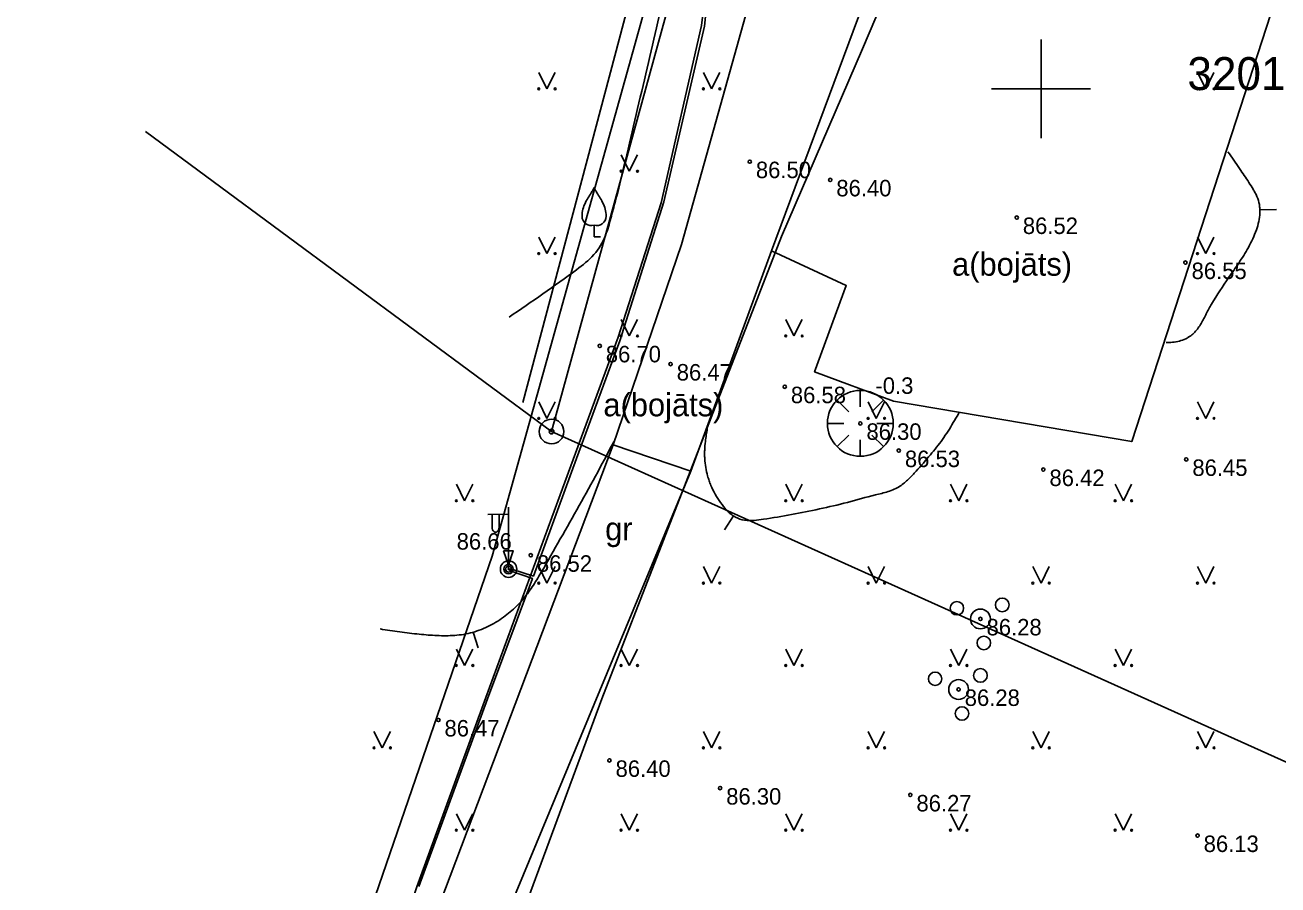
# Model space of a CAD drawing. Extents: x 576692 to 577659, y 273254 to 273799.
# Drawn here: x 576719.16 to 576757.19, y 273675.84 to 273701.94 of the extents above; entities that cross this region are included whole.
import ezdxf

# ---------------------------------------------------------------- set-up
doc = ezdxf.new("R2010")
doc.units = 0
for name, color, linetype in [('APGS_ELEM_####_####_#', 7, 'Continuous'), ('BUVE_EKAS_BPAL_####_#', 7, 'Continuous'), ('BUVE_EKAS_RAKS_TKST_#', 7, 'Continuous'), ('CELI_CAPM_####_####_#', 7, 'Continuous'), ('CELI_CMAL_####_####_#', 7, 'Continuous'), ('CELI_TAKA_####_####_#', 7, 'Continuous'), ('CKOM_ELEM_####_####_#', 7, 'Continuous'), ('GEOD_SITP_####_TKST_#', 7, 'Continuous'), ('HIDT_REZV_####_TKST_#', 7, 'Continuous'), ('LKAN_ELEM_PAST_TKST_#', 7, 'Continuous'), ('LKAN_VADP_PAST_####_#', 7, 'Continuous'), ('RELJ_ELEM_####_####_#', 7, 'Continuous'), ('ROBZ_PROJ_####_TKST_#', 7, 'Continuous'), ('SILT_VADP_UDEN_####_#', 7, 'Continuous'), ('TERT_DIAM_####_TKST_#', 7, 'Continuous'), ('TERT_KONT_####_####_#', 7, 'Continuous'), ('TERT_KRND_####_####_#', 7, 'Continuous'), ('UDTK_VADP_UDEN_TKST_#', 7, 'Continuous')]:
    doc.layers.add(name, color=color, linetype=linetype)

msp = doc.modelspace()

# ---------------------------------------------------------------- linework, layer by layer
at = {"layer": 'APGS_ELEM_####_####_#'}
msp.add_lwpolyline([(576737.011, 273689.199), (576739.373, 273688.394)], dxfattribs=at)
at = {"layer": 'BUVE_EKAS_RAKS_TKST_#'}
for radius in [0.375, 0.0702]:
    msp.add_circle((576735.14, 273689.6), radius, dxfattribs=at)
at = {"layer": 'CELI_CAPM_####_####_#'}
for points in [[(576748.236, 273714.891), (576752.784, 273713.881), (576754.719, 273717.805), (576756.542, 273719.356), (576769.187, 273719.688), (576767.146, 273715.06), (576764.561, 273707.822), (576760.708, 273708.626), (576758.033, 273705.522), (576752.756, 273689.295), (576745.525, 273690.518), (576743.128, 273691.407), (576744.089, 273694.027), (576741.816, 273695.089)], [(576747.985, 273714.221), (576746.348, 273707.285), (576741.816, 273695.089), (576739.373, 273688.394), (576733.496, 273674.256)], [(576731.578, 273674.82), (576737.011, 273689.199), (576739.086, 273695.273), (576742.568, 273707.72)]]:
    msp.add_lwpolyline(points, dxfattribs=at)
at = {"layer": 'CELI_TAKA_####_####_#'}
msp.add_lwpolyline([(576848.447, 273595.284), (576850.413, 273611.975), (576839.74, 273611.3), (576799.298, 273680.086), (576786.491, 273690.257), (576780.2, 273683.233), (576786.155, 273661.79), (576765.1, 273656.565), (576764.662, 273653.384), (576732.149, 273649.138), (576726.076, 273650.997), (576719.157, 273649.712), (576724.595, 273660.398), (576733.342, 273685.822), (576746.079, 273731.492)], dxfattribs=at)
at = {"layer": 'CKOM_ELEM_####_####_#'}
for p, q in [((576750, 273701.5), (576750, 273700)), ((576748.5, 273700), (576750, 273700)), ((576750, 273700), (576750, 273698.5)), ((576750, 273700), (576751.5, 273700))]:
    msp.add_line(p, q, dxfattribs=at)
at = {"layer": 'GEOD_SITP_####_TKST_#'}
for p, q in [((576757.144, 273696.337), (576756.644, 273696.324)), ((576740.392, 273686.617), (576740.661, 273687.038)), ((576732.909, 273683.033), (576732.763, 273683.511))]:
    msp.add_line(p, q, dxfattribs=at)
for points in [[(576743.18, 273721.579), (576742.673, 273719.416), (576742.4, 273718.16), (576742.151, 273716.898), (576741.901, 273715.637), (576741.627, 273714.381), (576741.252, 273712.992), (576740.821, 273711.619), (576740.384, 273710.247), (576739.993, 273708.863), (576739.309, 273706.065), (576738.651, 273703.26), (576738, 273700.452), (576737.339, 273697.647), (576737.081, 273696.597), (576736.938, 273696.074), (576736.779, 273695.554), (576736.425, 273694.968), (576735.899, 273694.512), (576733.849, 273693.07)], [(576755.676, 273698.093), (576756.029, 273697.579), (576756.31, 273697.162), (576756.44, 273696.955), (576756.498, 273696.848), (576756.553, 273696.738), (576756.628, 273696.486), (576756.642, 273696.358), (576756.644, 273696.232), (576756.612, 273695.974), (576756.537, 273695.718), (576756.295, 273695.19), (576756.001, 273694.709), (576755.696, 273694.272), (576755.179, 273693.469), (576755.096, 273693.325), (576755.018, 273693.177), (576754.941, 273693.029), (576754.86, 273692.883), (576754.666, 273692.617), (576754.543, 273692.507), (576754.472, 273692.46), (576754.394, 273692.418), (576753.994, 273692.308), (576753.795, 273692.3)], [(576747.518, 273690.181), (576747.491, 273690.135), (576747.335, 273689.871), (576747.009, 273689.36), (576746.641, 273688.895), (576746.209, 273688.397), (576745.978, 273688.157), (576745.853, 273688.046), (576745.718, 273687.943), (576745.356, 273687.778), (576744.97, 273687.677), (576744.121, 273687.449), (576743.271, 273687.25), (576742.421, 273687.08), (576741.571, 273686.936), (576741.288, 273686.902), (576741.003, 273686.911), (576740.725, 273687.001), (576740.59, 273687.089), (576740.524, 273687.145), (576740.46, 273687.211), (576740.11, 273687.698), (576739.978, 273687.966), (576739.924, 273688.107), (576739.879, 273688.252), (576739.791, 273688.775), (576739.787, 273688.906), (576739.789, 273689.037), (576739.811, 273689.298), (576739.868, 273689.693)], [(576737.032, 273689.301), (576737.016, 273689.27), (576736.472, 273688.243), (576735.91, 273687.226), (576735.335, 273686.216), (576734.755, 273685.208), (576734.481, 273684.781), (576734.164, 273684.39), (576733.787, 273684.043), (576733.57, 273683.887), (576733.332, 273683.745), (576732.811, 273683.526), (576732.541, 273683.457), (576732.266, 273683.419), (576731.731, 273683.406), (576731.197, 273683.442), (576730.606, 273683.511), (576730.013, 273683.596), (576729.942, 273683.608)]]:
    msp.add_spline(points, degree=3, dxfattribs=at)
at = {"layer": 'LKAN_ELEM_PAST_TKST_#'}
for p, q in [((576734.75, 273700.5), (576735, 273700)), ((576735, 273700), (576735.25, 273700.5)), ((576739.75, 273700.5), (576740, 273700)), ((576740, 273700), (576740.25, 273700.5)), ((576754.75, 273700.5), (576755, 273700)), ((576755, 273700), (576755.25, 273700.5)), ((576737.25, 273698), (576737.5, 273697.5)), ((576737.5, 273697.5), (576737.75, 273698)), ((576734.75, 273695.5), (576735, 273695)), ((576735, 273695), (576735.25, 273695.5)), ((576736.431, 273695.86), (576736.431, 273695.508)), ((576736.431, 273695.508), (576736.631, 273695.508)), ((576754.75, 273695.5), (576755, 273695)), ((576755, 273695), (576755.25, 273695.5)), ((576737.25, 273693), (576737.5, 273692.5)), ((576737.5, 273692.5), (576737.75, 273693)), ((576742.25, 273693), (576742.5, 273692.5)), ((576742.5, 273692.5), (576742.75, 273693)), ((576734.75, 273690.5), (576735, 273690)), ((576735, 273690), (576735.25, 273690.5)), ((576744.75, 273690.5), (576745, 273690)), ((576745, 273690), (576745.25, 273690.5)), ((576754.75, 273690.5), (576755, 273690)), ((576755, 273690), (576755.25, 273690.5)), ((576732.25, 273688), (576732.5, 273687.5)), ((576732.5, 273687.5), (576732.75, 273688)), ((576742.25, 273688), (576742.5, 273687.5)), ((576742.5, 273687.5), (576742.75, 273688)), ((576747.25, 273688), (576747.5, 273687.5)), ((576747.5, 273687.5), (576747.75, 273688)), ((576752.25, 273688), (576752.5, 273687.5)), ((576752.5, 273687.5), (576752.75, 273688)), ((576734.75, 273685.5), (576735, 273685)), ((576735, 273685), (576735.25, 273685.5)), ((576739.75, 273685.5), (576740, 273685)), ((576740, 273685), (576740.25, 273685.5)), ((576744.75, 273685.5), (576745, 273685)), ((576745, 273685), (576745.25, 273685.5)), ((576749.75, 273685.5), (576750, 273685)), ((576750, 273685), (576750.25, 273685.5)), ((576754.75, 273685.5), (576755, 273685)), ((576755, 273685), (576755.25, 273685.5)), ((576732.25, 273683), (576732.5, 273682.5)), ((576732.5, 273682.5), (576732.75, 273683)), ((576737.25, 273683), (576737.5, 273682.5)), ((576737.5, 273682.5), (576737.75, 273683)), ((576742.25, 273683), (576742.5, 273682.5)), ((576742.5, 273682.5), (576742.75, 273683)), ((576747.25, 273683), (576747.5, 273682.5)), ((576747.5, 273682.5), (576747.75, 273683)), ((576752.25, 273683), (576752.5, 273682.5)), ((576752.5, 273682.5), (576752.75, 273683)), ((576729.75, 273680.5), (576730, 273680)), ((576730, 273680), (576730.25, 273680.5)), ((576739.75, 273680.5), (576740, 273680)), ((576740, 273680), (576740.25, 273680.5)), ((576744.75, 273680.5), (576745, 273680)), ((576745, 273680), (576745.25, 273680.5)), ((576749.75, 273680.5), (576750, 273680)), ((576750, 273680), (576750.25, 273680.5)), ((576754.75, 273680.5), (576755, 273680)), ((576755, 273680), (576755.25, 273680.5)), ((576732.25, 273678), (576732.5, 273677.5)), ((576732.5, 273677.5), (576732.75, 273678)), ((576737.25, 273678), (576737.5, 273677.5)), ((576737.5, 273677.5), (576737.75, 273678)), ((576742.25, 273678), (576742.5, 273677.5)), ((576742.5, 273677.5), (576742.75, 273678)), ((576747.25, 273678), (576747.5, 273677.5)), ((576747.5, 273677.5), (576747.75, 273678)), ((576752.25, 273678), (576752.5, 273677.5)), ((576752.5, 273677.5), (576752.75, 273678))]:
    msp.add_line(p, q, dxfattribs=at)
for centre, radius in [((576734.75, 273700), 0.028), ((576735.25, 273700), 0.0263), ((576739.75, 273700), 0.028), ((576740.25, 273700), 0.0263), ((576754.75, 273700), 0.028), ((576755.25, 273700), 0.0263), ((576737.25, 273697.5), 0.028), ((576737.75, 273697.5), 0.0263), ((576734.75, 273695), 0.028), ((576735.25, 273695), 0.0263), ((576754.75, 273695), 0.028), ((576755.25, 273695), 0.0263), ((576737.25, 273692.5), 0.028), ((576737.75, 273692.5), 0.0263), ((576742.25, 273692.5), 0.028), ((576742.75, 273692.5), 0.0263), ((576734.75, 273690), 0.028), ((576735.25, 273690), 0.0263), ((576744.75, 273690), 0.028), ((576745.25, 273690), 0.0263), ((576754.75, 273690), 0.028), ((576755.25, 273690), 0.0263), ((576732.25, 273687.5), 0.028), ((576732.75, 273687.5), 0.0263), ((576742.25, 273687.5), 0.028), ((576742.75, 273687.5), 0.0263), ((576747.25, 273687.5), 0.028), ((576747.75, 273687.5), 0.0263), ((576752.25, 273687.5), 0.028), ((576752.75, 273687.5), 0.0263), ((576734.75, 273685), 0.028), ((576735.25, 273685), 0.0263), ((576739.75, 273685), 0.028), ((576740.25, 273685), 0.0263), ((576744.75, 273685), 0.028), ((576745.25, 273685), 0.0263), ((576749.75, 273685), 0.028), ((576750.25, 273685), 0.0263), ((576754.75, 273685), 0.028), ((576755.25, 273685), 0.0263), ((576748.822, 273684.338), 0.207), ((576747.447, 273684.237), 0.204), ((576748.161, 273683.913), 0.301), ((576748.264, 273683.185), 0.205), ((576732.25, 273682.5), 0.028), ((576732.75, 273682.5), 0.0263), ((576737.25, 273682.5), 0.028), ((576737.75, 273682.5), 0.0263), ((576742.25, 273682.5), 0.028), ((576742.75, 273682.5), 0.0263), ((576746.784, 273682.096), 0.204), ((576747.25, 273682.5), 0.028), ((576747.75, 273682.5), 0.0263), ((576748.159, 273682.197), 0.207), ((576752.25, 273682.5), 0.028), ((576752.75, 273682.5), 0.0263), ((576747.498, 273681.772), 0.301), ((576747.601, 273681.044), 0.205), ((576729.75, 273680), 0.028), ((576730.25, 273680), 0.0263), ((576739.75, 273680), 0.028), ((576740.25, 273680), 0.0263), ((576744.75, 273680), 0.028), ((576745.25, 273680), 0.0263), ((576749.75, 273680), 0.028), ((576750.25, 273680), 0.0263), ((576754.75, 273680), 0.028), ((576755.25, 273680), 0.0263), ((576732.25, 273677.5), 0.028), ((576732.75, 273677.5), 0.0263), ((576737.25, 273677.5), 0.028), ((576737.75, 273677.5), 0.0263), ((576742.25, 273677.5), 0.028), ((576742.75, 273677.5), 0.0263), ((576747.25, 273677.5), 0.028), ((576747.75, 273677.5), 0.0263), ((576752.25, 273677.5), 0.028), ((576752.75, 273677.5), 0.0263)]:
    msp.add_circle(centre, radius, dxfattribs=at)
for centre, radius, start, end in [((576749.056, 273689.112), 14.88, 148.4844, 149.9901), ((576736.014, 273697.146), 0.439, 324.3837, 341.712), ((576736.848, 273697.146), 0.439, 198.288, 215.6163), ((576723.806, 273689.112), 14.88, 30.0099, 31.5156), ((576736.955, 273696.133), 0.89, 151.757, 179.9138), ((576735.907, 273696.133), 0.89, 0.0862, 28.243), ((576736.355, 273696.139), 0.29, 181.0782, 285.2823), ((576736.507, 273696.139), 0.29, 254.7177, 358.9218)]:
    msp.add_arc(centre, radius, start, end, dxfattribs=at)
at = {"layer": 'RELJ_ELEM_####_####_#'}
for p, q in [((576743.807, 273690.555), (576744.161, 273690.201)), ((576744.514, 273690.848), (576744.514, 273690.348)), ((576744.868, 273690.201), (576745.221, 273690.555)), ((576743.514, 273689.848), (576744.014, 273689.848)), ((576745.014, 273689.848), (576745.514, 273689.848)), ((576743.807, 273689.141), (576744.161, 273689.494)), ((576744.868, 273689.494), (576745.221, 273689.141)), ((576744.514, 273689.348), (576744.514, 273688.848))]:
    msp.add_line(p, q, dxfattribs=at)
msp.add_lwpolyline([(576733.68, 273685.975), (576733.98, 273685.975), (576733.83, 273685.542)], close=True, dxfattribs=at)
for centre, radius in [((576741.158, 273697.79), 0.05), ((576743.6, 273697.237), 0.05), ((576749.262, 273696.095), 0.05), ((576754.385, 273694.727), 0.05), ((576736.602, 273692.2), 0.05), ((576738.755, 273691.648), 0.05), ((576742.219, 273690.96), 0.05), ((576744.514, 273689.848), 1), ((576744.514, 273689.848), 0.05), ((576745.682, 273689.021), 0.05), ((576754.409, 273688.753), 0.05), ((576750.07, 273688.445), 0.05), ((576734.511, 273685.845), 0.05), ((576748.161, 273683.913), 0.05), ((576747.498, 273681.772), 0.05), ((576731.704, 273680.845), 0.05), ((576736.898, 273679.62), 0.05), ((576740.257, 273678.778), 0.05), ((576746.032, 273678.571), 0.05), ((576754.752, 273677.339), 0.05)]:
    msp.add_circle(centre, radius, dxfattribs=at)
at = {"layer": 'ROBZ_PROJ_####_TKST_#'}
msp.add_lwpolyline([(576726.076, 273650.997), (576727.932, 273656.567), (576729.5, 273661.655), (576730.682, 273665.084), (576731.865, 273668.514), (576734.264, 273674.998), (576736.663, 273681.483), (576738.539, 273686.307), (576742.122, 273695.516), (576744.578, 273701.213), (576746.572, 273705.904), (576748.565, 273710.596)], dxfattribs=at)
at = {"layer": 'SILT_VADP_UDEN_####_#'}
for points in [[(576829.949, 273731.794), (576819.3, 273727.418), (576775.79, 273724.09), (576773.75, 273720.17), (576743.03, 273718.32), (576735.14, 273689.6), (576722.81, 273698.708)], [(576722.81, 273698.708), (576735.14, 273689.6), (576764.98, 273676.18), (576776.102, 273646.342)]]:
    msp.add_lwpolyline(points, dxfattribs=at)
msp.add_lwpolyline([(576735.14, 273689.6), (576743.03, 273718.32), (576773.75, 273720.17), (576765.79, 273703), (576762.48, 273692.95), (576762.24, 273683.67), (576764.98, 273676.18)], close=True, dxfattribs=at)
at = {"layer": 'TERT_DIAM_####_TKST_#'}
for p, q in [((576733.836, 273685.424), (576733.836, 273687.307)), ((576733.836, 273687.091), (576733.201, 273687.086)), ((576733.336, 273687.087), (576733.336, 273686.695)), ((576733.546, 273687.089), (576733.546, 273686.695))]:
    msp.add_line(p, q, dxfattribs=at)
for radius in [0.25, 0.09]:
    msp.add_circle((576733.836, 273685.424), radius, dxfattribs=at)
msp.add_ellipse((576733.441, 273686.695), major_axis=(0, 0.151), ratio=0.695971, start_param=1.570796, end_param=4.712389, dxfattribs=at)
at = {"layer": 'TERT_KONT_####_####_#'}
for radius in [0.141, 0.0126]:
    msp.add_circle((576733.836, 273685.424), radius, dxfattribs=at)
at = {"layer": 'TERT_KRND_####_####_#'}
for points in [[(576721.135, 273650.079), (576722.114, 273651.858), (576722.686, 273652.958), (576723.259, 273654.059), (576724.172, 273656.131), (576725.085, 273658.204), (576725.929, 273659.674), (576727.286, 273664.024), (576728.643, 273668.374), (576729.188, 273670.049), (576731.053, 273675.786), (576733.142, 273681.529), (576735.152, 273686.994), (576737.161, 273692.459), (576738.469, 273696.545), (576739.694, 273701.926), (576740.457, 273708.29), (576741.181, 273711.29), (576742.084, 273714.417), (576742.987, 273717.544), (576742.985, 273717.979), (576742.779, 273718.232), (576742.37, 273718.284)], [(576743.072, 273718.011), (576743.069, 273717.562), (576742.171, 273714.428), (576741.272, 273711.293), (576740.524, 273708.289), (576740.284, 273706.674), (576739.78, 273701.905), (576738.545, 273696.569), (576737.21, 273692.351), (576735.899, 273688.782), (576734.588, 273685.213), (576733.93, 273685.421), (576733.836, 273685.424), (576733.913, 273685.361), (576734.561, 273685.142), (576733.197, 273681.488), (576731.115, 273675.789)]]:
    msp.add_lwpolyline(points, dxfattribs=at)
at = {"layer": 'UDTK_VADP_UDEN_TKST_#'}
msp.add_lwpolyline([(576734.273, 273690.483), (576741.083, 273716.151)], dxfattribs=at)

# ---------------------------------------------------------------- texts
at = {"layer": 'BUVE_EKAS_BPAL_####_#'}
msp.add_text('32010020156', height=1, dxfattribs=at).set_placement((576754.445, 273699.963))
at = {"layer": 'CELI_CMAL_####_####_#'}
for s, p in [('a(bojāts)', (576747.3, 273694.329)), ('a(bojāts)', (576736.714, 273690.062)), ('gr', (576736.768, 273686.298))]:
    msp.add_text(s, height=0.7, dxfattribs=at).set_placement(p)
at = {"layer": 'HIDT_REZV_####_TKST_#'}
for s, p in [(' 86.50', (576741.158, 273697.29)), (' 86.40', (576743.6, 273696.737)), (' 86.52', (576749.262, 273695.595)), (' 86.55', (576754.385, 273694.227)), (' 86.70', (576736.602, 273691.7)), (' 86.47', (576738.755, 273691.148)), (' 86.58', (576742.219, 273690.46)), (' 86.30', (576744.514, 273689.348)), (' 86.53', (576745.682, 273688.521)), (' 86.45', (576754.409, 273688.253)), (' 86.42', (576750.07, 273687.945)), (' 86.66', (576732.074, 273686.016)), (' 86.52', (576734.511, 273685.345)), (' 86.28', (576748.161, 273683.413)), (' 86.28', (576747.498, 273681.272)), (' 86.47', (576731.704, 273680.345)), (' 86.40', (576736.898, 273679.12)), (' 86.30', (576740.257, 273678.278)), (' 86.27', (576746.032, 273678.071)), (' 86.13', (576754.752, 273676.839))]:
    msp.add_text(s, height=0.5, dxfattribs=at).set_placement(p)
at = {"layer": 'LKAN_VADP_PAST_####_#'}
msp.add_text('-0.3', height=0.5, dxfattribs=at).set_placement((576744.973, 273690.744))

doc.saveas('drawing.dxf')
